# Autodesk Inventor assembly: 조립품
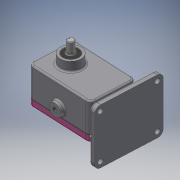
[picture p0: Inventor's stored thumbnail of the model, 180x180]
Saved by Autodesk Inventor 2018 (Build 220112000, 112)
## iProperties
Created: 2020-04
Part Number: 조립품
Document SubType Name: Assembly
Designer: 1class 18
Author: 1class 18
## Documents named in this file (11)
- C:\Users\1class 18\Desktop\700407V1036\조립품.iam
- C:\Users\1class 18\Desktop\700407V1036\개스킷.ipt
- C:\Users\1class 18\Desktop\700407V1036\메인축.ipt
- C:\Users\1class 18\Desktop\700407V1036\베어링부시.ipt
- C:\Users\1class 18\Desktop\700407V1036\본체.ipt
- C:\Users\1class 18\Desktop\700407V1036\볼트 M5.ipt
- C:\Users\1class 18\Desktop\700407V1036\서브축.ipt
- C:\Users\1class 18\Desktop\700407V1036\스퍼기어.ipt
- C:\Users\1class 18\Desktop\700407V1036\오일 실 16 28 7.ipt
- C:\Users\1class 18\Desktop\700407V1036\커버.ipt
- C:\Users\1class 18\Desktop\700407V1036\키 6 x 6 x 18.ipt
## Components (1 placed, 1 different names)
1. 개스킷:1
